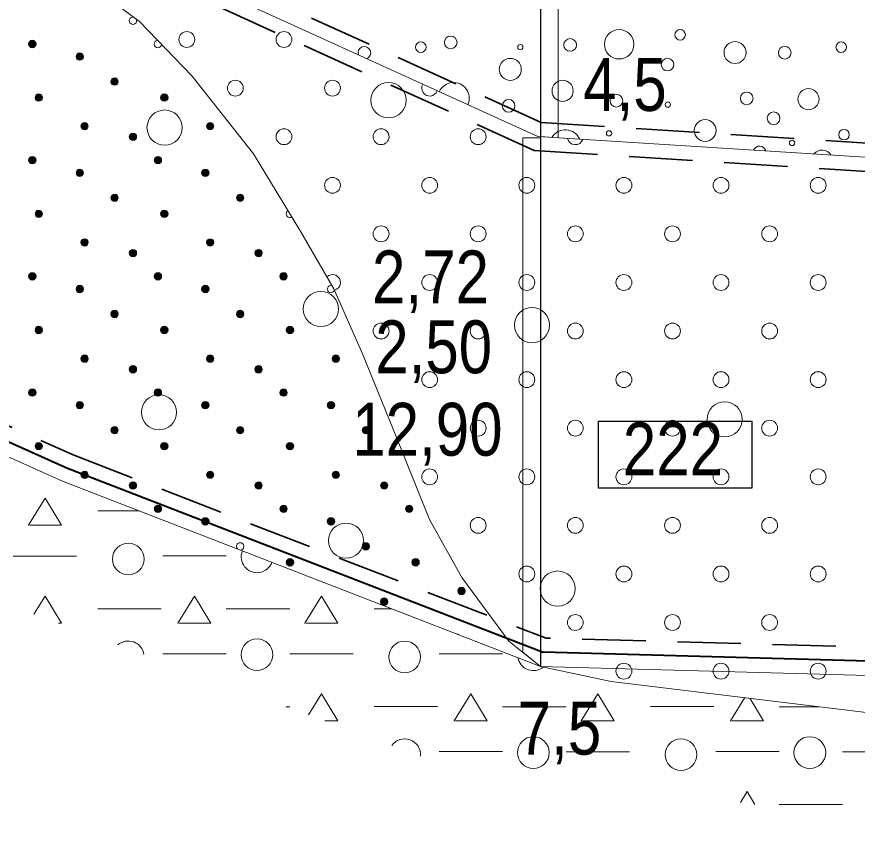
# Model space of a CAD drawing. Extents: x 640104 to 640970, y 6442278 to 6442689.
# Drawn here: x 640265.58 to 640313.3, y 6442350.05 to 6442396.62 of the extents above; entities that cross this region are included whole.
import ezdxf
from ezdxf.enums import TextEntityAlignment as Align

# ---------------------------------------------------------------- set-up
doc = ezdxf.new("R2010")
doc.units = 0
doc.header["$LTSCALE"] = 1.2
doc.linetypes.add('MEDIUM_DASHED', pattern=[4.5, 3, -1.5])
for name, color, linetype, lineweight in [('31', 7, 'Continuous', 13), ('32', 7, 'Continuous', 25), ('33', 7, 'Continuous', 13), ('35', 7, 'Continuous', 35), ('41', 7, 'Continuous', 13), ('42', 7, 'Continuous', 13), ('44', 7, 'Continuous', 13), ('46', 7, 'Continuous', 13), ('47', 7, 'Continuous', 13)]:
    doc.layers.add(name, color=color, linetype=linetype, lineweight=lineweight)

msp = doc.modelspace()

# ---------------------------------------------------------------- hatches: boundary and pattern name
at = {"layer": '44'}
for points in [[(640266.676, 6442395.08, 1), (640266.256, 6442395.08, 1)], [(640269.368, 6442394.365, 1), (640268.948, 6442394.365, 1)], [(640271.346, 6442392.946, 1), (640270.926, 6442392.946, 1)], [(640267.04, 6442392.038, 1), (640266.62, 6442392.038, 1)], [(640274.173, 6442392.038, 1), (640273.753, 6442392.038, 1)], [(640269.643, 6442390.412, 1), (640269.223, 6442390.412, 1)], [(640276.776, 6442390.412, 1), (640276.356, 6442390.412, 1)], [(640272.39, 6442389.807, 1), (640271.97, 6442389.807, 1)], [(640266.676, 6442388.484, 1), (640266.256, 6442388.484, 1)], [(640273.809, 6442388.484, 1), (640273.389, 6442388.484, 1)], [(640269.368, 6442387.769, 1), (640268.948, 6442387.769, 1)], [(640276.501, 6442387.769, 1), (640276.081, 6442387.769, 1)], [(640271.346, 6442386.35, 1), (640270.926, 6442386.35, 1)], [(640278.479, 6442386.35, 1), (640278.059, 6442386.35, 1)], [(640267.04, 6442385.442, 1), (640266.62, 6442385.442, 1)], [(640274.173, 6442385.442, 1), (640273.753, 6442385.442, 1)], [(640269.643, 6442383.816, 1), (640269.223, 6442383.816, 1)], [(640276.776, 6442383.816, 1), (640276.356, 6442383.816, 1)], [(640272.39, 6442383.211, 1), (640271.97, 6442383.211, 1)], [(640279.523, 6442383.211, 1), (640279.103, 6442383.211, 1)], [(640266.676, 6442381.888, 1), (640266.256, 6442381.888, 1)], [(640273.809, 6442381.888, 1), (640273.389, 6442381.888, 1)], [(640280.942, 6442381.888, 1), (640280.522, 6442381.888, 1)], [(640269.368, 6442381.173, 1), (640268.948, 6442381.173, 1)], [(640276.501, 6442381.173, 1), (640276.081, 6442381.173, 1)], [(640271.346, 6442379.754, 1), (640270.926, 6442379.754, 1)], [(640278.479, 6442379.754, 1), (640278.059, 6442379.754, 1)], [(640267.04, 6442378.846, 1), (640266.62, 6442378.846, 1)], [(640274.173, 6442378.846, 1), (640273.753, 6442378.846, 1)], [(640281.306, 6442378.846, 1), (640280.886, 6442378.846, 1)], [(640269.643, 6442377.22, 1), (640269.223, 6442377.22, 1)], [(640276.776, 6442377.22, 1), (640276.356, 6442377.22, 1)], [(640283.909, 6442377.22, 1), (640283.489, 6442377.22, 1)], [(640272.39, 6442376.615, 1), (640271.97, 6442376.615, 1)], [(640279.523, 6442376.615, 1), (640279.103, 6442376.615, 1)], [(640266.676, 6442375.292, 1), (640266.256, 6442375.292, 1)], [(640273.809, 6442375.292, 1), (640273.389, 6442375.292, 1)], [(640280.942, 6442375.292, 1), (640280.522, 6442375.292, 1)], [(640269.368, 6442374.577, 1), (640268.948, 6442374.577, 1)], [(640276.501, 6442374.577, 1), (640276.081, 6442374.577, 1)], [(640283.634, 6442374.577, 1), (640283.214, 6442374.577, 1)], [(640271.346, 6442373.158, 1), (640270.926, 6442373.158, 1)], [(640278.479, 6442373.158, 1), (640278.059, 6442373.158, 1)], [(640285.612, 6442373.158, 1), (640285.192, 6442373.158, 1)], [(640267.04, 6442372.25, 1), (640266.62, 6442372.25, 1)], [(640274.173, 6442372.25, 1), (640273.753, 6442372.25, 1)], [(640281.306, 6442372.25, 1), (640280.886, 6442372.25, 1)], [(640269.643, 6442370.624, 1), (640269.223, 6442370.624, 1)], [(640276.776, 6442370.624, 1), (640276.356, 6442370.624, 1)], [(640283.909, 6442370.624, 1), (640283.489, 6442370.624, 1)], [(640272.39, 6442370.019, 1), (640271.97, 6442370.019, 1)], [(640279.523, 6442370.019, 1), (640279.103, 6442370.019, 1)], [(640286.656, 6442370.019, 1), (640286.236, 6442370.019, 1)], [(640273.809, 6442368.696, 1), (640273.389, 6442368.696, 1)], [(640280.942, 6442368.696, 1), (640280.522, 6442368.696, 1)], [(640288.075, 6442368.696, 1), (640287.655, 6442368.696, 1)], [(640276.501, 6442367.981, 1), (640276.081, 6442367.981, 1)], [(640283.634, 6442367.981, 1), (640283.214, 6442367.981, 1)], [(640285.612, 6442366.562, 1), (640285.192, 6442366.562, 1)], [(640281.306, 6442365.654, 1), (640280.886, 6442365.654, 1)], [(640288.439, 6442365.654, 1), (640288.019, 6442365.654, 1)], [(640291.042, 6442364.028, 1), (640290.622, 6442364.028, 1)], [(640286.656, 6442363.423, 1), (640286.236, 6442363.423, 1)]]:
    msp.add_hatch(color=256, dxfattribs=at).paths.add_polyline_path(points)

# ---------------------------------------------------------------- linework, layer by layer
at = {"layer": '31'}
for points in [[(640139.08, 6442423.82), (640151.96, 6442423.75), (640173.66, 6442421.26), (640213.16, 6442416.61), (640233.94, 6442414.53), (640242.79, 6442413.66), (640295.17, 6442389.83), (640328.15, 6442387.74), (640358.78, 6442385.66), (640377.96, 6442384.87), (640391.41, 6442383.72), (640397.31, 6442383.01), (640414.42, 6442381.45)], [(640256.77, 6442407.3), (640258.78, 6442405.81), (640262.17, 6442403.54), (640264.64, 6442402), (640267.42, 6442400.15), (640272.56, 6442396.35), (640275.54, 6442393.26), (640279.03, 6442388.84), (640281.71, 6442384.42), (640283.58, 6442381.19), (640285.22, 6442377.49), (640286.95, 6442373.22), (640289.01, 6442368.08), (640290.86, 6442364.79), (640293.53, 6442361.19), (640295.32, 6442359.75)], [(640139.08, 6442391.74), (640152, 6442391.74), (640184.83, 6442387.53), (640224.44, 6442383.27), (640230.93, 6442382.67), (640242.81, 6442381.6), (640246.59, 6442379.93), (640268.17, 6442370.27), (640295.32, 6442359.75), (640299.34, 6442358.9), (640322.09, 6442356.12), (640340.84, 6442354.22), (640374.54, 6442350.71), (640388.93, 6442348.78), (640409.14, 6442347), (640414.32, 6442346.47), (640439.11, 6442345.27), (640478.03, 6442341.77)]]:
    msp.add_lwpolyline(points, dxfattribs=at)
at = {"layer": '32'}
msp.add_line((640295.32, 6442434.75), (640295.32, 6442359.75), dxfattribs=at)
at = {"layer": '33'}
for points in [[(640296.32, 6442389.75), (640296.32, 6442431.49), (640295.36, 6442431.67), (640295.32, 6442431.67), (640295.32, 6442389.82)], [(640294.32, 6442389.75), (640294.32, 6442360.56), (640295.32, 6442359.75), (640295.32, 6442389.75), (640295.17, 6442389.75)]]:
    msp.add_lwpolyline(points, close=True, dxfattribs=at)
at = {"layer": '33', "lineweight": 25}
msp.add_lwpolyline([(640298.61, 6442373.67), (640307.32, 6442373.67), (640307.32, 6442369.87), (640298.61, 6442369.87)], close=True, dxfattribs=at)
at = {"layer": '35', "linetype": 'MEDIUM_DASHED'}
for points in [[(640153.52, 6442424.38), (640173.75, 6442422.06), (640213.24, 6442417.41), (640234.02, 6442415.33), (640243, 6442414.44), (640295.36, 6442390.62), (640328.2, 6442388.54), (640358.82, 6442386.46), (640378.01, 6442385.67), (640391.49, 6442384.52), (640397.4, 6442383.81), (640411.83, 6442382.49)], [(640153.52, 6442422.77), (640173.56, 6442420.47), (640213.07, 6442415.82), (640233.86, 6442413.74), (640242.58, 6442412.88), (640294.97, 6442389.04), (640328.09, 6442386.94), (640358.73, 6442384.86), (640377.91, 6442384.07), (640391.32, 6442382.92), (640397.23, 6442382.22), (640405.71, 6442381.44)], [(640153.52, 6442393.16), (640185.01, 6442389.12), (640224.6, 6442384.86), (640231.07, 6442384.26), (640243.22, 6442383.17), (640247.24, 6442381.39), (640268.78, 6442371.75), (640295.64, 6442361.35)], [(640518.62, 6442352.3), (640414.65, 6442358.06), (640295.64, 6442361.35)]]:
    msp.add_lwpolyline(points, dxfattribs=at)
at = {"layer": '35', "lineweight": 40}
for points in [[(640152.72, 6442392.46), (640184.92, 6442388.33), (640224.52, 6442384.07), (640231, 6442383.47), (640243.02, 6442382.39), (640246.92, 6442380.66), (640268.47, 6442371.01), (640295.48, 6442360.55)], [(640518.52, 6442351.5), (640414.61, 6442357.26), (640295.48, 6442360.55)]]:
    msp.add_lwpolyline(points, dxfattribs=at)
at = {"layer": '35', "lineweight": 13}
msp.add_lwpolyline([(640519.42, 6442350.65), (640414.58, 6442356.46), (640295.32, 6442359.75)], dxfattribs=at)
at = {"layer": '41'}
for centre, radius in [((640290.226, 6442395.166), 0.36), ((640299.789, 6442395.062), 0.834), ((640303.247, 6442395.6), 0.3), ((640288.528, 6442394.901), 0.3), ((640294.175, 6442394.901), 0.15), ((640297.006, 6442395.023), 0.36), ((640306.369, 6442394.594), 0.624), ((640312.397, 6442394.901), 0.3), ((640309.188, 6442394.579), 0.36), ((640293.606, 6442393.637), 0.624), ((640302.534, 6442393.914), 0.36), ((640296.578, 6442392.417), 0.6), ((640299.635, 6442391.856), 0.36), ((640307.035, 6442391.993), 0.36), ((640310.537, 6442391.949), 0.6), ((640293.511, 6442391.569), 0.36), ((640302.551, 6442391.64), 0.15), ((640308.554, 6442390.861), 0.36), ((640304.673, 6442390.169), 0.624), ((640312.553, 6442389.93), 0.3), ((640299.215, 6442390.008), 0.15), ((640309.607, 6442389.465), 0.15)]:
    msp.add_circle(centre, radius, dxfattribs=at)
for centre, radius, start, end in [((640285.319, 6442394.579), 0.36, 292.2059, 198.8642), ((640290.386, 6442392.005), 0.889, 335.4288, 155.6413), ((640296.729, 6442389.315), 0.893, 23.8634, 148.8961), ((640307.762, 6442388.924), 0.36, 13.626, 159.1336), ((640311.311, 6442388.454), 0.6, 32.2646, 140.4949)]:
    msp.add_arc(centre, radius, start, end, dxfattribs=at)
at = {"layer": '42'}
for centre in [(640275.238, 6442395.331), (640280.754, 6442395.331), (640277.996, 6442392.573), (640283.511, 6442392.573), (640280.754, 6442389.815), (640286.269, 6442389.815), (640291.784, 6442389.815), (640283.511, 6442387.058), (640289.027, 6442387.058), (640294.542, 6442387.058), (640300.058, 6442387.058), (640305.573, 6442387.058), (640311.088, 6442387.058), (640286.269, 6442384.3), (640291.784, 6442384.3), (640297.3, 6442384.3), (640302.815, 6442384.3), (640308.331, 6442384.3), (640289.027, 6442381.542), (640294.542, 6442381.542), (640300.058, 6442381.542), (640305.573, 6442381.542), (640311.088, 6442381.542), (640286.269, 6442378.785), (640291.784, 6442378.785), (640297.3, 6442378.785), (640302.815, 6442378.785), (640308.331, 6442378.785), (640289.027, 6442376.027), (640294.542, 6442376.027), (640300.058, 6442376.027), (640305.573, 6442376.027), (640311.088, 6442376.027), (640291.784, 6442373.269), (640297.3, 6442373.269), (640302.815, 6442373.269), (640308.331, 6442373.269), (640289.027, 6442370.511), (640294.542, 6442370.511), (640300.058, 6442370.511), (640305.573, 6442370.511), (640311.088, 6442370.511), (640291.784, 6442367.754), (640297.3, 6442367.754), (640302.815, 6442367.754), (640308.331, 6442367.754), (640294.542, 6442364.996), (640300.058, 6442364.996), (640305.573, 6442364.996), (640311.088, 6442364.996), (640297.3, 6442362.238), (640302.815, 6442362.238), (640308.331, 6442362.238), (640300.058, 6442359.481), (640305.573, 6442359.481), (640311.088, 6442359.481)]:
    msp.add_circle(centre, 0.45, dxfattribs=at)
for centre, start, end in [((640289.027, 6442392.573), 149.9754, 341.0947), ((640297.3, 6442389.815), 192.2223, 340.5372), ((640283.511, 6442381.542), 283.3661, 135.4598)]:
    msp.add_arc(centre, 0.45, start, end, dxfattribs=at)
at = {"layer": '44'}
for centre in [(640266.466, 6442395.08), (640269.158, 6442394.365), (640271.136, 6442392.946), (640266.83, 6442392.038), (640273.963, 6442392.038), (640269.433, 6442390.412), (640276.566, 6442390.412), (640272.18, 6442389.807), (640266.466, 6442388.484), (640273.599, 6442388.484), (640269.158, 6442387.769), (640276.291, 6442387.769), (640271.136, 6442386.35), (640278.269, 6442386.35), (640266.83, 6442385.442), (640273.963, 6442385.442), (640269.433, 6442383.816), (640276.566, 6442383.816), (640272.18, 6442383.211), (640279.313, 6442383.211), (640266.466, 6442381.888), (640273.599, 6442381.888), (640280.732, 6442381.888), (640269.158, 6442381.173), (640276.291, 6442381.173), (640271.136, 6442379.754), (640278.269, 6442379.754), (640266.83, 6442378.846), (640273.963, 6442378.846), (640281.096, 6442378.846), (640269.433, 6442377.22), (640276.566, 6442377.22), (640283.699, 6442377.22), (640272.18, 6442376.615), (640279.313, 6442376.615), (640266.466, 6442375.292), (640273.599, 6442375.292), (640280.732, 6442375.292), (640269.158, 6442374.577), (640276.291, 6442374.577), (640283.424, 6442374.577), (640271.136, 6442373.158), (640278.269, 6442373.158), (640285.402, 6442373.158), (640266.83, 6442372.25), (640273.963, 6442372.25), (640281.096, 6442372.25), (640269.433, 6442370.624), (640276.566, 6442370.624), (640283.699, 6442370.624), (640272.18, 6442370.019), (640279.313, 6442370.019), (640286.446, 6442370.019), (640273.599, 6442368.696), (640280.732, 6442368.696), (640287.865, 6442368.696), (640276.291, 6442367.981), (640283.424, 6442367.981), (640285.402, 6442366.562), (640281.096, 6442365.654), (640288.229, 6442365.654), (640290.832, 6442364.028), (640286.446, 6442363.423)]:
    msp.add_circle(centre, 0.21, dxfattribs=at)
for centre, start, end in [((640272.18, 6442396.403), 84.289, 22.7082), ((640273.599, 6442395.08), 95.1491, 352.9088), ((640281.096, 6442385.442), 122.4934, 299.8252), ((640283.424, 6442381.173), 77.9442, 338.3095), ((640278.269, 6442366.562), 273.4373, 224.2131), ((640290.557, 6442361.385), 49.4962, 88.1541)]:
    msp.add_arc(centre, 0.21, start, end, dxfattribs=at)
at = {"layer": '46'}
for p, q in [((640272.54, 6442368.58), (640270.18, 6442368.58)), ((640268.98, 6442366.01), (640265.38, 6442366.01)), ((640277.48, 6442366.02), (640273.88, 6442366.02)), ((640273.78, 6442363.02), (640270.18, 6442363.02)), ((640281.08, 6442363.02), (640277.48, 6442363.02)), ((640286.88, 6442363.02), (640285.88, 6442363.02)), ((640277.48, 6442360.46), (640273.88, 6442360.46)), ((640284.68, 6442360.46), (640281.08, 6442360.46)), ((640293.17, 6442360.46), (640289.57, 6442360.46)), ((640281.08, 6442357.46), (640280.86, 6442357.46)), ((640289.48, 6442357.47), (640285.88, 6442357.47)), ((640296.77, 6442357.46), (640293.17, 6442357.46)), ((640305.17, 6442357.47), (640301.57, 6442357.47)), ((640311.12, 6442357.46), (640308.87, 6442357.46)), ((640293.17, 6442354.91), (640289.57, 6442354.91)), ((640300.37, 6442354.9), (640296.77, 6442354.9)), ((640308.87, 6442354.91), (640305.27, 6442354.91)), ((640316.07, 6442354.9), (640312.47, 6442354.9)), ((640312.47, 6442351.91), (640308.87, 6442351.91))]:
    msp.add_line(p, q, dxfattribs=at)
for points in [[(640266.24, 6442367.74), (640266.24, 6442367.77), (640267.19, 6442369.3), (640268.12, 6442367.76), (640266.32, 6442367.77)], [(640266.56, 6442362.72), (640267.19, 6442363.74), (640268.12, 6442362.2), (640267.96, 6442362.2)], [(640274.72, 6442362.19), (640274.72, 6442362.21), (640275.67, 6442363.74), (640276.6, 6442362.2), (640274.8, 6442362.21)], [(640281.94, 6442362.19), (640281.94, 6442362.21), (640282.89, 6442363.74), (640283.82, 6442362.2), (640282.02, 6442362.21)], [(640282.15, 6442356.99), (640282.89, 6442358.19), (640283.82, 6442356.65), (640283.07, 6442356.65)], [(640290.41, 6442356.64), (640290.41, 6442356.66), (640291.36, 6442358.19), (640292.29, 6442356.65), (640290.49, 6442356.66)], [(640297.63, 6442356.64), (640297.64, 6442356.66), (640298.58, 6442358.19), (640299.51, 6442356.65), (640297.71, 6442356.66)], [(640306.11, 6442356.64), (640306.11, 6442356.66), (640306.92, 6442357.98)], [(640307.21, 6442357.94), (640307.99, 6442356.65), (640306.19, 6442356.66)], [(640306.68, 6442352.03), (640307.06, 6442352.64), (640307.49, 6442351.91)]]:
    msp.add_lwpolyline(points, dxfattribs=at)
for centre in [(640271.912, 6442365.844), (640279.225, 6442360.412), (640287.607, 6442360.289), (640294.92, 6442354.857), (640303.302, 6442354.735), (640310.615, 6442354.857)]:
    msp.add_circle(centre, 0.9, dxfattribs=at)
for centre, start, end in [((640279.225, 6442365.966), 157.5788, 340.0716), ((640271.912, 6442360.289), 8.7603, 130.8808), ((640294.92, 6442360.412), 190.3349, 309.4412), ((640287.607, 6442354.735), 354.9375, 144.7036)]:
    msp.add_arc(centre, 0.9, start, end, dxfattribs=at)
at = {"layer": '47'}
for centre in [(640286.69, 6442391.888), (640273.976, 6442390.334), (640282.848, 6442380.036), (640294.836, 6442379.121), (640273.659, 6442374.174), (640305.779, 6442373.771), (640284.274, 6442366.886), (640296.295, 6442364.165)]:
    msp.add_circle(centre, 1, dxfattribs=at)

# ---------------------------------------------------------------- texts
at = {"layer": '32', "width": 0.85}
for s, p in [('4,5', (640300.115, 6442391.28)), ('7,5', (640296.4, 6442354.74))]:
    msp.add_text(s, height=3, dxfattribs=at).set_placement(p, align=Align.CENTER)
at = {"layer": '33', "width": 0.85}
for s, p in [('2,72', (640289.075, 6442380.36)), ('2,50', (640289.255, 6442376.39)), ('12,90', (640288.9, 6442371.71)), ('222', (640302.84, 6442370.6))]:
    msp.add_text(s, height=3, dxfattribs=at).set_placement(p, align=Align.CENTER)

doc.saveas('drawing.dxf')
